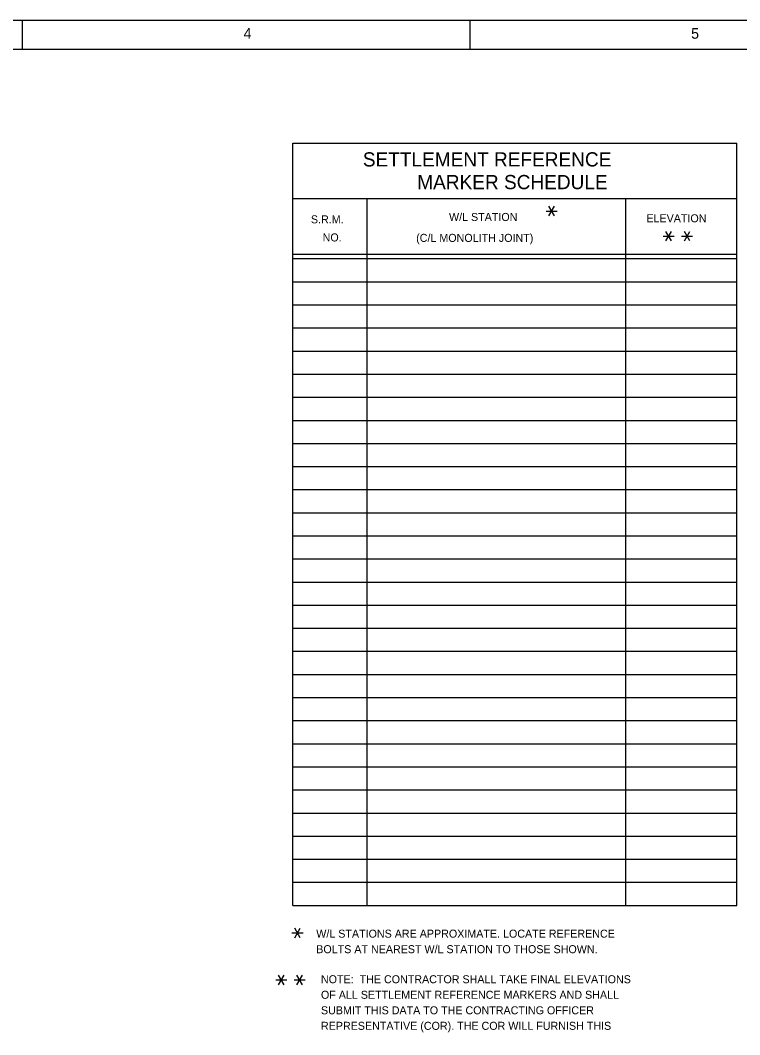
# Model space of a CAD drawing. Extents: x 44742.55 to 44745.38, y 44738.95 to 44741.13.
# Drawn here: x 44744.16 to 44744.97, y 44739.989 to 44741.132 of the extents above; entities that cross this region are included whole.
import ezdxf

# ---------------------------------------------------------------- set-up
doc = ezdxf.new("R2010")
doc.units = 0
for name, color, linetype in [('Level 1', 7, 'Continuous'), ('Level 10', 7, 'Continuous'), ('Level 3', 7, 'Continuous'), ('Level 4', 7, 'Continuous'), ('Level 9', 7, 'Continuous'), ('S-GRID-HORZ', 7, 'Continuous'), ('S-GRID-VERT', 7, 'Continuous')]:
    doc.layers.add(name, color=color, linetype=linetype)

msp = doc.modelspace()

# ---------------------------------------------------------------- linework, layer by layer
at = {"layer": 'Level 1'}
msp.add_lwpolyline([(44742.553, 44741.1323), (44745.3804, 44741.1323), (44745.3804, 44738.947), (44742.553, 44738.947)], close=True, dxfattribs=at)
at = {"layer": 'Level 10'}
for p, q in [((44744.1621, 44741.0999), (44744.1621, 44741.1323)), ((44744.6664, 44741.0999), (44744.6664, 44741.1323)), ((44744.4668, 44740.9938), (44744.9668, 44740.9938)), ((44744.4668, 44740.1344), (44744.4668, 44740.9938)), ((44744.9668, 44740.1344), (44744.9668, 44740.9938)), ((44744.4668, 44740.9313), (44744.9668, 44740.9313)), ((44744.4668, 44740.1344), (44744.9668, 44740.1344))]:
    msp.add_line(p, q, dxfattribs=at)
at = {"layer": 'Level 4'}
for p, q in [((44744.7552, 44740.9118), (44744.7615, 44740.9226)), ((44744.7615, 44740.9118), (44744.7552, 44740.9226)), ((44744.7521, 44740.9172), (44744.7646, 44740.9172)), ((44744.8838, 44740.8889), (44744.8963, 44740.8889)), ((44744.8869, 44740.8835), (44744.8932, 44740.8943)), ((44744.8932, 44740.8835), (44744.8869, 44740.8943)), ((44744.9046, 44740.8889), (44744.9171, 44740.8889)), ((44744.9078, 44740.8835), (44744.914, 44740.8943)), ((44744.914, 44740.8835), (44744.9078, 44740.8943)), ((44744.4687, 44740.098), (44744.4749, 44740.1088)), ((44744.4749, 44740.098), (44744.4687, 44740.1088)), ((44744.4656, 44740.1034), (44744.4781, 44740.1034)), ((44744.4473, 44740.0505), (44744.4598, 44740.0505)), ((44744.4505, 44740.0451), (44744.4567, 44740.0559)), ((44744.4567, 44740.0451), (44744.4505, 44740.0559)), ((44744.4682, 44740.0505), (44744.4807, 44740.0505)), ((44744.4713, 44740.0451), (44744.4775, 44740.0559)), ((44744.4775, 44740.0451), (44744.4713, 44740.0559))]:
    msp.add_line(p, q, dxfattribs=at)
at = {"layer": 'Level 9'}
msp.add_line((44742.6494, 44741.0999), (44745.1714, 44741.0999), dxfattribs=at)
at = {"layer": 'S-GRID-HORZ'}
for p, q in [((44744.4668, 44740.8688), (44744.9668, 44740.8688)), ((44744.4668, 44740.8636), (44744.9668, 44740.8636)), ((44744.4668, 44740.8376), (44744.9668, 44740.8376)), ((44744.4668, 44740.8376), (44744.9668, 44740.8376)), ((44744.4668, 44740.8115), (44744.9668, 44740.8115)), ((44744.4668, 44740.7855), (44744.9668, 44740.7855)), ((44744.4668, 44740.7594), (44744.9668, 44740.7594)), ((44744.4668, 44740.7334), (44744.9668, 44740.7334)), ((44744.4668, 44740.7073), (44744.9668, 44740.7073)), ((44744.4668, 44740.6813), (44744.9668, 44740.6813)), ((44744.4668, 44740.6553), (44744.9668, 44740.6553)), ((44744.4668, 44740.6292), (44744.9668, 44740.6292)), ((44744.4668, 44740.6032), (44744.9668, 44740.6032)), ((44744.4668, 44740.5771), (44744.9668, 44740.5771)), ((44744.4668, 44740.5511), (44744.9668, 44740.5511)), ((44744.4668, 44740.5251), (44744.9668, 44740.5251)), ((44744.4668, 44740.499), (44744.9668, 44740.499)), ((44744.4668, 44740.473), (44744.9668, 44740.473)), ((44744.4668, 44740.4469), (44744.9668, 44740.4469)), ((44744.4668, 44740.4209), (44744.9668, 44740.4209)), ((44744.4668, 44740.3949), (44744.9668, 44740.3949)), ((44744.4668, 44740.3688), (44744.9668, 44740.3688)), ((44744.4668, 44740.3428), (44744.9668, 44740.3428)), ((44744.4668, 44740.3167), (44744.9668, 44740.3167)), ((44744.4668, 44740.2907), (44744.9668, 44740.2907)), ((44744.4668, 44740.2647), (44744.9668, 44740.2647)), ((44744.4668, 44740.2386), (44744.9668, 44740.2386)), ((44744.4668, 44740.2126), (44744.9668, 44740.2126)), ((44744.4668, 44740.1865), (44744.9668, 44740.1865)), ((44744.4668, 44740.1605), (44744.9668, 44740.1605))]:
    msp.add_line(p, q, dxfattribs=at)
at = {"layer": 'S-GRID-VERT'}
for p, q in [((44744.5502, 44740.1344), (44744.5502, 44740.9313)), ((44744.8418, 44740.1344), (44744.8418, 44740.9313))]:
    msp.add_line(p, q, dxfattribs=at)

# ---------------------------------------------------------------- texts
at = {"layer": 'Level 1'}
for s, p in [('4', (44744.4111, 44741.1115)), ('5', (44744.9154, 44741.1115))]:
    msp.add_text(s, height=0.012, dxfattribs=at).set_placement(p)
at = {"layer": 'Level 3'}
for s, p in [('SETTLEMENT REFERENCE', (44744.5455, 44740.9675)), ('MARKER SCHEDULE', (44744.6068, 44740.9419))]:
    msp.add_text(s, height=0.01604, dxfattribs=at).set_placement(p)
at = {"layer": 'Level 4'}
for s, p in [('S.R.M.', (44744.487, 44740.9034)), ('W/L STATION', (44744.6426, 44740.9061)), ('ELEVATION', (44744.865, 44740.9046)), ('NO.', (44744.5002, 44740.883)), ('(C/L MONOLITH JOINT)', (44744.6056, 44740.8825)), ('W/L STATIONS ARE APPROXIMATE. LOCATE REFERENCE', (44744.493, 44740.0981)), ('BOLTS AT NEAREST W/L STATION TO THOSE SHOWN.', (44744.493, 44740.0806)), ('NOTE:  THE CONTRACTOR SHALL TAKE FINAL ELEVATIONS', (44744.4983, 44740.0467)), ('OF ALL SETTLEMENT REFERENCE MARKERS AND SHALL', (44744.4983, 44740.0292)), ('SUBMIT THIS DATA TO THE CONTRACTING OFFICER', (44744.4983, 44740.0117)), ('REPRESENTATIVE (COR). THE COR WILL FURNISH THIS', (44744.4983, 44739.9942))]:
    msp.add_text(s, height=0.00902, dxfattribs=at).set_placement(p)

doc.saveas('drawing.dxf')
